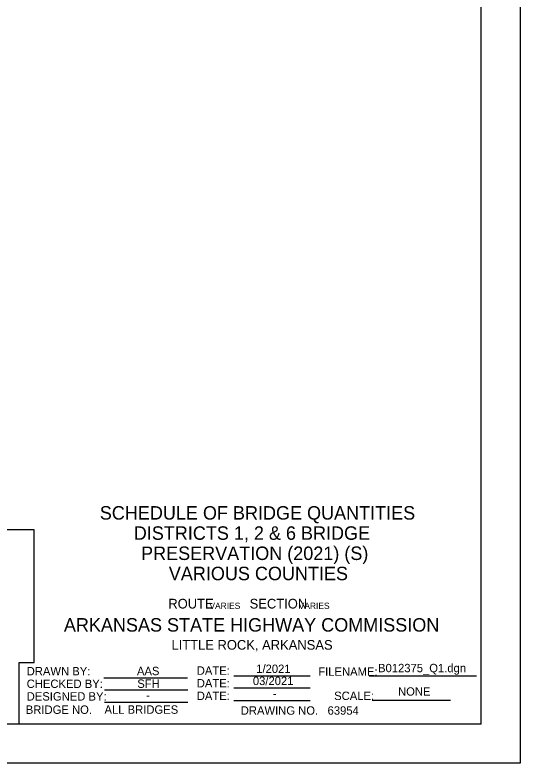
# Model space of a CAD drawing. Extents: x 16 to 1228740, y 11 to 152440.
# Drawn here: x 17.864 to 18.49, y 10.709 to 11.637 of the extents above; entities that cross this region are included whole.
import ezdxf

# ---------------------------------------------------------------- set-up
doc = ezdxf.new("R2010")
doc.units = 0
for name, color, linetype in [('B_Copy In', 7, 'Continuous'), ('B_Text', 7, 'Continuous'), ('B_Title Text', 7, 'Continuous'), ('R_Border', 7, 'Continuous'), ('R_No Plot', 7, 'Continuous')]:
    doc.layers.add(name, color=color, linetype=linetype)

msp = doc.modelspace()

# ---------------------------------------------------------------- linework, layer by layer
at = {"layer": 'B_Text'}
for p, q in [((17.97449, 10.81515), (18.07809, 10.81515)), ((18.13559, 10.81765), (18.23009, 10.81765)), ((18.30318, 10.81765), (18.43623, 10.81765)), ((17.97509, 10.80015), (18.07869, 10.80015)), ((18.13559, 10.80265), (18.23009, 10.80265)), ((18.13559, 10.80265), (18.23009, 10.80265)), ((17.97509, 10.78515), (18.07869, 10.78515)), ((18.13559, 10.78703), (18.23009, 10.78703)), ((18.30706, 10.78765), (18.40419, 10.78765))]:
    msp.add_line(p, q, dxfattribs=at)
at = {"layer": 'R_Border'}
for q in [(18.44221, 12.49475), (15.78327, 10.75755)]:
    msp.add_line((18.44221, 10.75755), q, dxfattribs=at)
msp.add_lwpolyline([(15.65694, 12.54282), (18.49027, 12.54282), (18.49027, 10.70949), (15.65694, 10.70949)], close=True, dxfattribs=at)
at = {"layer": 'R_No Plot'}
for p, q in [((17.888, 10.99864), (17.47349, 10.99864)), ((17.888, 10.83424), (17.888, 10.99864)), ((17.86946, 10.83424), (17.888, 10.83424)), ((17.86946, 10.75755), (17.86946, 10.83424))]:
    msp.add_line(p, q, dxfattribs=at)

# ---------------------------------------------------------------- texts
at = {"layer": 'B_Copy In'}
for s, height, p in [('SCHEDULE OF BRIDGE QUANTITIES', 0.0167, (17.96944, 11.01141)), ('DISTRICTS 1, 2 & 6 BRIDGE', 0.0167, (18.01154, 10.98636)), ('PRESERVATION (2021) (S)', 0.0167, (18.02058, 10.96131)), ('VARIOUS COUNTIES', 0.0167, (18.05496, 10.93626)), ('AAS', 0.0104, (18.0155, 10.81846)), ('1/2021', 0.0104, (18.16332, 10.82119)), ('B012375_Q1.dgn', 0.0104, (18.31434, 10.8221)), ('SFH', 0.0104, (18.01587, 10.80273)), ('03/2021', 0.0104, (18.15915, 10.80619)), ('NONE', 0.0104, (18.3391, 10.79302)), ('-', 0.0104, (18.02672, 10.78846)), ('-', 0.0104, (18.184, 10.79057)), ('ALL BRIDGES', 0.0104166, (17.97523, 10.7706)), ('63954', 0.010417, (18.25173, 10.76944))]:
    msp.add_text(s, height=height, dxfattribs=at).set_placement(p)
at = {"layer": 'B_Text'}
for s, height, p in [('DRAWN BY:', 0.010417, (17.87879, 10.8182)), ('DATE:', 0.010417, (18.08959, 10.8189)), ('FILENAME:', 0.010417, (18.24018, 10.81765)), ('CHECKED BY:', 0.0104166, (17.87879, 10.80257)), ('DATE:', 0.010417, (18.08959, 10.80328)), ('DESIGNED BY:', 0.0104166, (17.87879, 10.78695)), ('DATE:', 0.010417, (18.08959, 10.78765)), ('SCALE:', 0.010417, (18.25989, 10.78765)), ('BRIDGE NO.', 0.010417, (17.87767, 10.77048)), ('DRAWING NO.', 0.0104166, (18.14412, 10.76942))]:
    msp.add_text(s, height=height, dxfattribs=at).set_placement(p)
at = {"layer": 'B_Title Text'}
for s, height, p in [('ROUTE          SECTION ', 0.012, (18.0544, 10.90115)), ('                VARIES                         VARIES', 0.0078, (18.05893, 10.90059)), ('ARKANSAS STATE HIGHWAY COMMISSION', 0.0167, (17.92492, 10.8725)), ('LITTLE ROCK, ARKANSAS', 0.012, (18.05823, 10.85007))]:
    msp.add_text(s, height=height, dxfattribs=at).set_placement(p)

doc.saveas('drawing.dxf')
